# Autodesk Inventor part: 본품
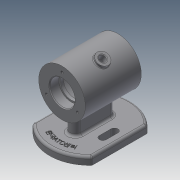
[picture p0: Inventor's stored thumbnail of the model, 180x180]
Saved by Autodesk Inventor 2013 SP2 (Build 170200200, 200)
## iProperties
Created: 2022-02
Part Number: 본품
Material: Generic
Document SubType Name: Modeling
Designer: aa
Density: 1 g/cm^3
Mass: 183.424 g
Surface Area: 489.745 cm^2
Volume: 183.424 cm^3
Author: aa
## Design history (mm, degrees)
sketch "스케치1"
  geometry: L1 (-36, 0)-(36, 0); L2 (-36, 0)-(-36, 30); L3 (-36, 30)-(36, 30); L4 (36, 30)-(36, 0); L5 (-36, 16)-(-24, 16); L6 (-24, 16)-(-24, 14); L7 (-24, 14)-(-20, 14); L8 (-20, 14)-(-20, 25); L9 (-20, 25)-(20, 25); L10 (20, 25)-(20, 14); L11 (20, 14)-(24, 14); L12 (24, 14)-(24, 16); L13 (24, 16)-(36, 16); 2 further points
  constraints: 26 end point, 7 parallel, 5 perpendicular, 2 point on line, 1 coincident, 1 horizontal, 1 midpoint
  dimensions: "d0" = 72 distance of L1.start L1.end; "d1" = 60 diameter of L3 L1; "d2" = 12 distance of L5.start L5.end; "d3" = 12 distance of L12.end L13.end; "d4" = 40 distance of L8.end L9.end; "d5" = 4 distance of L6.end L7.end; "d6" = 32 diameter of L5 L1; "d7" = 28 diameter of L7 L1; "d8" = 50 diameter of L9 L1; "d9" = 28 diameter of L11 L1; "d10" = 32 diameter of L13 L1
revolve "회전1" sketch "스케치1" stored, may be unused: angle "d11" = 90 deg
sketch "스케치2"
  geometry: C1 r 30 at (0, 0) reference; 1 further point
  constraints: 1 vertical alignment
  dimensions: "d12" = 23 distance of C1.centre point (0, 23)
hole "구멍1" sketch "스케치2" at (0, 23) diameter "d13" = 3.242; stored, may be unused: countersink angle "d17" = 90 deg, drill point angle "d19" = 118 deg; dims "d14" = 8, "d15" = 4, "d16" = 2, "d18" = 10
node "작업 평면1"
sketch "스케치3"
  geometry: L1 (35.496, -38)-(-35.496, -38); L2 (35.496, 38)-(-35.496, 38); A1 r 52 centre (0, 0) between (35.496, -38) and (35.496, 38); A2 r 52 centre (0, 0) between (-35.496, 38) and (-35.496, -38); 3 further points
  constraints: 4 end point, 4 point on circle, 2 centre point, 2 midpoint, 1 coincident, 1 horizontal, 1 parallel, 1 vertical alignment
  dimensions: "d25" = 76 distance between parallel lines of L2 L1; "d26" = 52 radius of A1; "d27" = 38 distance from line of point (0, 0) L1
extrude "돌출1" join sketch "스케치3" distance "d28" = 10; taper "d29" = 0 deg
sketch "스케치4"
  geometry: L1 (-19, 7)-(19, 7); L2 (19, 7)-(19, -7); L3 (19, -7)-(-19, -7); L4 (-19, -7)-(-19, 7); L5 (-19, 7)-(19, -7); L6 (19, 7)-(-19, -7); A1 r 52 centre (0, 0) between (35.496, -38) and (35.496, 38) reference; A2 r 7 centre (-19, 0) between (-19, 7) and (-19, -7); A3 r 7 centre (19, 0) between (19, -7) and (19, 7)
  constraints: 12 end point, 4 point on circle, 4 tangent, 2 centre point, 2 midpoint, 2 parallel, 1 horizontal, 1 perpendicular
  dimensions: "d30" = 38 distance of L2.end L3.end; "d31" = 14 distance of L1.end L2.end
extrude "돌출2" join sketch "스케치4" stored distance "d32" = 10; taper "d33" = 0 deg
sketch "스케치5"
  geometry: L1 (-7.5, 28.5)-(7.5, 28.5); L2 (7.5, 28.5)-(7.5, 19.5); L3 (7.5, 19.5)-(-7.5, 19.5); L4 (-7.5, 19.5)-(-7.5, 28.5); L5 (-7.5, 28.5)-(7.5, 19.5); L6 (7.5, 28.5)-(-7.5, 19.5); A1 r 52 centre (0, 0) between (-35.496, 38) and (-35.496, -38) reference; A2 r 4.5 centre (-7.5, 24) between (-7.5, 28.5) and (-7.5, 19.5); A3 r 4.5 centre (7.5, 24) between (7.5, 19.5) and (7.5, 28.5); 2 further points
  constraints: 12 end point, 4 point on circle, 4 tangent, 3 midpoint, 2 centre point, 2 parallel, 1 horizontal, 1 perpendicular, 1 vertical alignment
  dimensions: "d34" = 15 distance of L2.end L3.end; "d35" = 9 distance of L1.end L2.end; "d36" = 24 distance of A1.centre point (0, 24)
extrude "돌출3" cut sketch "스케치5" stored distance "d37" = 10; taper "d38" = 0 deg
sketch "스케치6"
  geometry: L1 (-29.172, -7)-(-52, -7) reference; L2 (-52, -7)-(-52, -19.5) reference; L3 (-52, -19.5)-(-62, -19.5) reference; L4 (-62, -19.5)-(-62, 19.5) reference; L5 (-62, 19.5)-(-52, 19.5) reference; L6 (-52, 19.5)-(-52, 7) reference; L7 (-52, 7)-(-29.172, 7) reference; L8 (-62, 38)-(-52, 38) reference; L9 (-52, 38)-(-52, 28.5) reference; L10 (-52, 28.5)-(-62, 28.5) reference; L11 (-62, 28.5)-(-62, 38) reference; L12 (-52, -38)-(-62, -38) reference; L13 (-62, -38)-(-62, -28.5) reference; L14 (-62, -28.5)-(-52, -28.5) reference; L15 (-52, -28.5)-(-52, -38) reference; L16 (0, 0)-(28.579, 16.5); L17 (0, 0)-(33, 0); C1 r 25 at (0, 0) reference; A1 r 30 centre (0, 0) between (-29.172, -7) and (-29.172, 7) reference; 2 further points
  constraints: 4 end point, 1 coincident, 1 equal length, 1 horizontal
  dimensions: "d39" = 33 distance of L16.start L16.end; "d40" = 30 deg angle of L17 L16
  node "절단 모서리 투영1"
node "작업 평면2"
sketch "스케치7"
  geometry: C1 r 8 at (0, 0); 1 further point
  constraints: 1 centre point, 1 coincident
  dimensions: "d41" = 16 diameter of C1
extrude "돌출4" join sketch "스케치7" stored distance "d42" = 10; taper "d43" = 0 deg
sketch "스케치8"
  geometry: C1 r 8 at (0, 0) reference; 1 further point
  constraints: 1 coincident
hole "구멍2" sketch "스케치8" at (0, 0) diameter "d44" = 8; stored, may be unused: countersink angle "d48" = 90 deg, drill point angle "d50" = 118 deg; dims "d45" = 8, "d46" = 4, "d47" = 2, "d49" = 10
fillet "모깎기1" dims "d51" = 3, "d52" = 0.3
chamfer "모따기1" distance "d53" = 1; stored, may be unused: second distance "d54" = 2, angle "d55" = 45 deg
fillet "모깎기2" dims "d56" = 1
fillet "모깎기3" dims "d57" = 3
fillet "모깎기4" dims "d58" = 3
fillet "모깎기5" dims "d59" = 3
sketch "스케치9"
  geometry: C1 r 42.5 at (0, 0); A1 r 49 centre (0, 0) between (34.293, -35) and (34.293, 35) reference
  constraints: 1 centre point, 1 coincident, 1 other
  dimensions: "d60" = 85 diameter of C1
feature "엠보싱1" sketch "스케치9" dims "d0" = 72, "d1" = 60, "d2" = 12, "d3" = 12, "d4" = 40, "d5" = 4, "d6" = 32, "d7" = 28, "d8" = 50, "d9" = 28, "d10" = 32, "d19" = 118 deg, "d61" = 0.5, "d62" = 0
fillet "모깎기6" dims "d63" = 1
node "솔리드1"
pattern_circular "원형 패턴1" dims angle "d21" = 360 deg
mirror "대칭1"
mirror "대칭2"
other parameters: "d23" = -62, "d24" = 104
